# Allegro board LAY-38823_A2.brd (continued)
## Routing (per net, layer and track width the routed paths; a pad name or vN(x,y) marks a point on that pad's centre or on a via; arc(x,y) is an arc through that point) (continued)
ONOFF: length 23.2
  TOP w0.104: U1.A25 28.99,35.8 29.35,36.16 29.35,37.58 30.83,39.06 TP7.1 v1(31.38,40.19) 31.73,40.54 R21.2
  L3_IN1 w0.081: v1(31.38,40.19) 31.38,40.88 32.68,42.18 32.68,42.68 32.13,43.23 28.47,43.23 26.03,45.67 26.03,46.14 25.33,46.84 24.83,46.84 24.41,47.26 24.41,47.76 23.62,48.55 v1(22.78,48.55)
  BOTTOM w0.104: J4.46 22.47,49.18 22.78,48.86 v1(22.78,48.55)
PDM_CLK: length 21.2
  TOP w0.076: U1.AC15 24.44,24.71 v1(24.46,24.69)
  L3_IN1 w0.081: v1(24.46,24.69) 24.12,24.36 24.12,22.62 35.13,11.62 v1(35.28,11.62)
  BOTTOM w0.104: J5.65 34.85,11.19 v1(35.28,11.62)
PDM_DATA0: length 24.5
  TOP w0.076: U1.AD18 25.08,24.21 v1(25.03,24.15)
  L3_IN1 w0.081: v1(25.03,24.15) 25.13,24.05 25.13,22.24 34.99,12.37 35.43,12.37 37.22,10.58 v1(37.22,8.13)
  BOTTOM w0.104: v1(37.22,8.13) 35.61,8.13 35.25,8.48 J5.67
PDM_DATA1: length 20.7
  TOP w0.102: U1.AC14 v1(23.49,24.24)
  L3_IN1 w0.081: v1(35.27,10.32) 35.27,10.81 23.49,22.59 v1(23.49,24.24)
  BOTTOM w0.104: v1(35.27,10.32) 35.27,10.3 35.65,9.92 J5.69
PDM_DATA2: length 21.8
  TOP w0.076: v1(22.54,24.15) 22.59,24.21 U1.AD13
  L3_IN1 w0.081: v1(36.05,9.71) 35.06,9.71 34.69,10.08 34.69,10.8 22.64,22.85 22.64,24.06 v1(22.54,24.15)
  BOTTOM w0.104: J5.71 v1(36.05,9.71)
PDM_DATA3: length 23
  TOP w0.076: v1(22.54,24.71) 22.54,24.71 U1.AC13
  L3_IN1 w0.081: v1(22.54,24.71) 22.92,24.33 22.92,22.87 34.9,10.88 34.9,10.16 35.12,9.95 35.68,9.95 v1(36.05,10.32)
  BOTTOM w0.104: v1(36.05,10.32) 36.45,9.92 J5.73
PHY_VREF: length 1.9
  TOP w0.076: TP58.1 15.95,28.17 U1.P1
PMIC_NINT: length 37
  TOP w0.076: U1.AF13 23.25,22.96 23.25,22.53
  TOP w0.104: v1(24.51,17.14) 24.51,17.88 23.2,19.19 23.2,22.48 23.25,22.53
  TOP w0.203: U8.13 5.85,8.54 v2(5.74,8.43)
  BOTTOM w0.104: v2(5.74,8.43) 6.19,8.43 6.33,8.3 6.33,6.94 7.43,5.84 12.42,5.84 13.3,6.72 19.88,6.72 20.88,7.72 20.88,13.23 23.93,16.28 23.93,16.56 v1(24.51,17.14)
  BOTTOM w0.254: R61.1 5.19,8.43 v2(5.74,8.43)
PMIC_ON_REQ: length 87.7
  TOP w0.104: R51.1 18.48,15.42 18.67,15.42 19.2,15.95 19.2,18.04 17.46,19.79 14.73,19.79 13.59,20.93 2.44,20.93 1.31,22.06 v1(1.31,35.72) ; TP6.1 32.89,42.44 v1(32.1,42.44) 31.29,42.44 29.96,41.11 29.96,38.88 28.89,37.81 28.89,36.2 28.49,35.8 U1.A24
  L3_IN1 w0.081: v1(23.42,48.03) 23.42,47.66 24.88,46.2 24.88,45.73 27.79,42.82 31.72,42.82 v1(32.1,42.44)
  BOTTOM w0.104: J4.48 22.87,49.1 23.16,48.81 23.16,48.29 v1(23.42,48.03) 22.81,47.42 12.67,47.42 1.31,36.05 v1(1.31,35.72)
PMIC_STBY_REQ: length 69.9
  TOP w0.076: U1.E24 28.08,33.71 v1(28.06,33.7)
  TOP w0.104: v2(18.79,16.18) 18.69,16.08 R52.1 ; v1(23.27,7.76) 23.27,8.5 TP10.1 v2(19.33,8.72)
  L3_IN1 w0.076: 31.63,31.74 31.04,31.74 29.09,33.7 v1(28.06,33.7)
  L3_IN1 w0.081: 31.63,31.74 32.1,31.74 32.85,32.49 33.83,32.49 35.04,33.71 35.47,33.71 v1(35.86,33.31)
  BOTTOM w0.104: v1(35.86,33.31) 37.62,31.56 37.62,14.24 41.97,9.89 41.97,8.55 41.47,8.05 40.12,8.05 39.56,7.49 27.82,7.49 27.55,7.76 v1(23.27,7.76) ; v2(19.33,8.72) 19.52,8.91 19.52,15.5 18.85,16.18 v2(18.79,16.18)
POR_B: length 81.5
  TOP w0.076: U1.B24 28.75,35.46 28.75,35.81 29.12,36.18 29.12,37.49
  TOP w0.104: v1(24.04,47.57) 24.04,48.1 22.7,49.44 12.99,49.44 0.89,37.33 0.89,20.21 1.55,19.55 1.55,12.9 1.8,12.65 3.07,12.65 3.96,11.76 3.96,10.62 R114.2 ; 29.12,37.49 29.12,37.71 30.2,38.8 30.2,40.37 TP9.1 v1(31.39,41.55) 31.49,41.66 R20.2
  L3_IN1 w0.081: v1(24.04,47.57) 24.04,47.34 25.12,46.26 25.12,45.92 28.02,43.02 32.04,43.02 32.47,42.6 32.47,42.29 31.73,41.55 v1(31.39,41.55)
  BOTTOM w0.104: v1(24.04,47.57) 23.8,47.81 23.8,48.19 23.4,48.6 23.4,48.97 23.27,49.09 J4.50
QSPIA_DATA0: length 30.2
  TOP w0.076: U1.P23 v1(28.45,29.21)
  TOP w0.104: v1(40.99,42.48) 42.65,42.48 43.59,43.42 TP16.1
  L3_IN1 w0.081: v1(40.99,42.48) 41.24,42.23 41.24,39.78 40.52,39.06 40.52,34.85 38.32,32.65 38.32,32 35.53,29.21 v1(28.45,29.21)
  BOTTOM w0.104: U5.5 43.69,43.84 42.33,42.48 v1(40.99,42.48)
QSPIA_DATA1: length 27.6
  TOP w0.076: v1(28.59,30.74) 28.49,30.74 28.37,30.85 28.37,31.09 U1.K24
  L3_IN1 w0.081: v1(39.9,40.95) 39.9,40.39 39.45,39.94 39.45,36.54 37.24,34.33 37.24,32.53 34.99,30.28 29.95,30.28 29.32,30.91 28.77,30.91 28.6,30.74 v1(28.59,30.74)
  BOTTOM w0.104: v1(39.9,40.95) 39.95,40.9 39.95,40.8 41.16,39.6 45.63,39.6 46.23,39 U5.2
QSPIA_DATA2: length 26.8
  TOP w0.076: U1.K23 27.96,31.18 27.96,30.83 v1(28.03,30.76)
  L3_IN1 w0.081: v1(28.03,30.76) 28.03,30.98 28.17,31.12 29.69,31.12 30.18,30.63 35.05,30.63 37.03,32.61 37.03,34.59 39.22,36.78 39.22,40.35 v1(39.49,40.62)
  BOTTOM w0.104: v1(39.49,40.62) 39.49,40.6 41.65,38.44 42.63,38.44 43,38.08 44.55,38.08 44.96,38.49 U5.3
QSPIA_DATA3: length 28.7
  TOP w0.076: v1(28.05,30.16) 27.99,30.1 U1.N23
  L3_IN1 w0.081: v1(28.05,30.16) 28.38,29.83 35.13,29.83 37.78,32.48 37.78,34.08 40.05,36.35 40.05,39.59 40.82,40.36 40.82,41.22 40.68,41.36 v1(40.66,41.36)
  BOTTOM w0.104: U5.7 46.23,44.19 45.37,43.33 43.97,43.33 42,41.37 40.66,41.37 v1(40.66,41.36)
QSPIA_NSS0: length 29.7
  TOP w0.076: v1(28.6,30.17) 28.49,30.07 U1.N24
  L3_IN1 w0.081: v1(28.6,30.17) 28.72,30.05 35.06,30.05 37.57,32.57 37.57,34.2 39.66,36.3 39.66,39.74 40.45,40.53 v1(40.45,40.87)
  BOTTOM w0.104: R37.2 48.45,38.92 48.28,38.76 U5.1 47.5,39.02 46.66,39.85 41.47,39.85 v1(40.45,40.87)
QSPIA_SCLK: length 33.9
  TOP w0.076: U1.N22 v1(27.49,30.16)
  TOP w0.104: TP17.1 43.53,42.1 40.66,42.1 v1(40.64,42.08)
  L3_IN1 w0.081: v1(40.64,42.08) 40.69,42.08 41.03,41.73 41.03,40.1 40.27,39.34 40.27,34.93 38.03,32.68 38.03,32.26 35.32,29.55 28.1,29.55 v1(27.49,30.16)
  BOTTOM w0.104: U5.6 44.96,44.23 44.41,43.67 43.98,43.67 42.38,42.08 v1(40.64,42.08)
R_SNSP1: length 5.4
  TOP w0.203: U8.38 14.45,11.74 15.74,13.03 R193.2 R194.1
R_SNSP2: length 4.5
  TOP w0.203: R192.2 14.94,16.13 R191.1 12.5,15.11 12.21,14.82 U8.44
REF_CLK_32K: length 68.3
  TOP w0.104: U1.AG14 23.49,19.7 v1(24.93,18.27) ; v1(29.68,7.1) 30.09,7.51 R116.1
  L3_IN1 w0.081: v1(24.93,18.27) 30.78,12.41 30.78,8.21 v1(29.68,7.1)
  BOTTOM w0.104: R115.1 47.76,32.86 40.02,25.12 40.02,12.74 42.48,10.27 42.48,8.24 41.34,7.1 v1(29.68,7.1)
REG_PD_B: length 47.7
  TOP w0.076: U1.R23 v1(27.99,28.26)
  TOP w0.104: U9.12 63.72,36.29 59.95,40.06 50.75,40.06 48.53,37.84 48.53,32.33 47.38,31.18 42.9,31.18 40.09,28.37 38.96,28.37 38.53,27.94 36.12,27.94 v2(36,28.05)
  BOTTOM w0.076: 31.63,28.6 28.34,28.6 v1(27.99,28.26)
  BOTTOM w0.104: v2(36,28.05) 36,28.19 35.59,28.6 31.63,28.6
RF_ANT0: length 19.7
  TOP w0.279: J1.1 68.1,3.68 C457.1 C455.2
RTC_RESET_B: length 110.2
  TOP w0.076: v1(28.58,32.79) 28.57,32.79 28.49,32.86 U1.F24
  TOP w0.104: v2(4.57,11.05) 4.37,11.25 R111.2 ; v1(38.33,37.67) 38.33,39.14 39.08,39.89 39.08,42.49 38.95,42.62 TP8.1 39.25,43.68 R102.2 ; v2(20.09,5.79) 20.09,6.05 20.88,6.83 27.5,6.83 29.12,5.21 29.12,4.1 29.89,3.33 37.11,3.33 40.67,6.88 v1(40.67,7.67)
  L3_IN1 w0.081: v1(28.58,32.79) 28.65,32.79 28.66,32.8 29.71,32.8 30.98,31.54 32.19,31.54 32.93,32.29 35.87,32.29 36.23,32.65 36.23,35.57 v1(38.33,37.67)
  BOTTOM w0.104: v1(40.67,7.67) 41.46,7.67 42.2,8.41 42.2,10.06 37.94,14.33 37.94,34.94 38.33,35.34 v1(38.33,37.67) ; v2(4.57,11.05) 2.59,9.07 2.59,4.11 4.31,2.39 18.41,2.39 20.09,4.07 v2(20.09,5.79)
SAI2_MCLK: length 29
  TOP w0.076: v1(26.5,24.17) 26.43,24.17 26.39,24.21 U1.AD19
  L3_IN1 w0.081: v1(26.5,24.17) 26.42,24.09 26.42,21.58 35.18,12.83 35.56,12.83 37.86,10.53 37.86,5.61 36.35,4.09 35.75,4.09 35.25,4.6 v1(35.25,4.62)
  BOTTOM w0.104: J5.66 34.85,5.55 35.03,5.38 35.03,4.84 v1(35.25,4.62)
SAI2_RXC: length 21.7
  TOP w0.076: v1(27.45,25.69) 27.49,25.65 U1.AB22
  L3_IN1 w0.076: 28.7,25.02 30.06,23.65 30.06,21.21
  L3_IN1 w0.081: v1(32.3,18.75) 30.06,20.99 30.06,21.21 ; v1(27.45,25.69) 28.13,25.02 28.7,25.02
  BOTTOM w0.104: v1(32.3,18.75) 37.65,13.4 J5.79
SAI2_RXD: length 38.9
  TOP w0.076: v1(28.49,24.23) 28.49,24.24 U1.AC24
  L3_IN1 w0.081: v1(28.49,24.23) 28.04,23.79 28.04,21.14 31.1,18.08 39.03,18.08 40.3,19.35 v1(40.82,19.35)
  BOTTOM w0.104: v1(40.82,19.35) 41.16,19.7 41.16,24.82 48.13,31.78 R132.2
SAI2_RXD_RES: length 1.9
  TOP w0.104: v2(54.63,32.08) 54.6,32.12 U9.25
  BOTTOM w0.104: R132.1 54.53,31.78 54.63,31.89 v2(54.63,32.08)
SAI2_RXFS: length 28.9
  TOP w0.076: v1(26.49,24.73) 26.47,24.71 U1.AC19
  L3_IN1 w0.081: v1(35.41,5.19) 35.41,4.98 35.62,4.77 35.62,4.52 35.84,4.3 36.26,4.3 37.59,5.63 37.59,10.51 35.51,12.58 35.12,12.58 26.15,21.55 26.15,24.39 v1(26.49,24.73)
  BOTTOM w0.104: v1(35.41,5.19) 35.41,5.28 35.25,5.44 J5.68
SAI2_TXC: length 41.1
  TOP w0.076: v1(27.06,24.33) 27.18,24.21 U1.AD22
  L3_IN1 w0.081: v1(27.06,24.33) 27.14,24.25 27.14,21.16 30.84,17.46 39.86,17.46 v1(40.81,18.4)
  BOTTOM w0.104: v1(40.81,18.4) 41.39,18.99 41.39,24.65 48.17,31.43 52.05,31.43 52.27,31.21 R198.1 53.28,30.7 R131.2
SAI2_TXC_1P8: length 69.7
  TOP w0.104: v1(40.82,17.56) 41.17,17.21 41.17,6.6 37.64,3.07 26.52,3.07 25.68,3.91 25.68,5.49 24.61,6.55 21.89,6.55 21.51,6.17 21.51,3.66 20.91,3.06 19.96,3.06 19.32,3.69 18.42,3.69 17.61,4.5 R196.2 17.61,5.93 16.48,7.06 13.17,7.06 12.78,6.67 12.43,6.67 12.21,6.89 U8.27
  BOTTOM w0.104: v1(40.82,17.56) 41.62,18.37 41.62,24.51 47.82,30.7 R198.2
SAI2_TXC_3P3: length 30.2
  TOP w0.104: R203.1 v2(15.75,3.43)
  L3_IN1 w0.081: v2(15.75,3.43) 15.99,3.68 37.45,3.68 39.08,5.31 v2(39.08,9.85)
  BOTTOM w0.104: J5.87 39.25,9.68 v2(39.08,9.85)
SAI2_TXC_RES: length 2
  TOP w0.104: U9.26 54.47,31.22 v2(54.62,31.06)
  BOTTOM w0.104: R131.1 54.38,30.7 54.62,30.95 v2(54.62,31.06)
SAI2_TXD: length 40.7
  TOP w0.076: U1.AC22 27.26,24.71 v1(27.08,24.89)
  L3_IN1 w0.081: v1(27.08,24.89) 27.43,24.54 27.43,21.16 30.93,17.67 39.46,17.67 40.57,18.78 42.42,18.78 v1(42.48,18.84)
  BOTTOM w0.104: R130.2 R199.1 52.25,29.05 52.03,28.82 46.65,28.82 42.13,24.3 42.13,19.19 v1(42.48,18.84)
SAI2_TXD_1P8: length 66.2
  TOP w0.104: v1(42.5,18.31) 42.22,18.02 40.31,18.02 38.56,16.27 38.56,5.86 36.31,3.61 30.92,3.61 30.03,4.49 30.03,4.88 29.9,5.02 29.9,5.39 27.63,7.65 25.03,7.65 24.44,7.06 20.55,7.06 v2(19.26,5.78) ; v2(16.71,5.05) 16.65,5.1 16.65,5.28 R197.2 16.27,5.57 16.02,5.82 16.02,6.53 15.77,6.78 13.38,6.78 13.04,6.44 12.25,6.44 11.81,6.89 U8.26
  L3_IN1 w0.081: v2(19.26,5.78) 18.53,5.05 v2(16.71,5.05)
  BOTTOM w0.104: v1(42.5,18.31) 42.47,18.31 41.86,18.92 41.86,24.41 47.08,29.63 R199.2
SAI2_TXD_3P3: length 32.5
  TOP w0.104: R202.1 v2(14.68,3.4)
  L3_IN1 w0.081: v2(14.68,3.4) 15.16,3.88 36.48,3.88 38.68,6.09 38.68,10.06 v2(39.06,10.44)
  BOTTOM w0.104: J5.91 40.05,9.55 40.07,9.57 40.07,10 39.63,10.44 v2(39.06,10.44)
SAI2_TXD_RES: length 2
  TOP w0.104: v2(54.6,30.1) 54.38,30.32 U9.27
  BOTTOM w0.104: R130.1 54.25,29.63 54.6,29.98 v2(54.6,30.1)
SAI2_TXFS: length 38.2
  TOP w0.076: v1(28.01,24.65) 28.01,24.56 27.99,24.54 U1.AD23
  L3_IN1 w0.081: v1(42.51,19.39) 42.1,18.98 40.31,18.98 39.2,17.88 31.02,17.88 27.81,21.08 27.81,24.45 v1(28.01,24.65)
  BOTTOM w0.104: R129.2 46.86,28.56 42.42,24.12 42.42,19.49 v1(42.51,19.39)
SAI2_TXFS_RES: length 2.2
  TOP w0.104: v2(54.64,29.26) 54.48,29.42 U9.28
  BOTTOM w0.104: v2(54.64,29.26) 54.64,29.11 54.09,28.56 R129.1
SAI3_MCLK: length 19.9
  TOP w0.076: U1.AD6 19.87,24.21 19.9,24.17 v1(19.96,24.17)
  L3_IN1 w0.081: v1(29.65,10.32) 29.72,10.38 29.72,12.96 19.89,22.78 19.89,24.1 v1(19.96,24.17)
  BOTTOM w0.104: v1(29.65,10.32) 29.65,9.93 30.05,9.53 J5.41
SAI3_RXC: length 22
  TOP w0.104: v1(32.38,9.77) 32.34,9.82 32.34,9.83 30.1,12.06 24.75,12.06 19.99,16.82 U1.AG7
  BOTTOM w0.104: J5.53 32.45,9.7 v1(32.38,9.77)
SAI3_RXD: length 22.8
  TOP w0.076: U1.AF7 20.24,22.96 20.24,22.49
  TOP w0.104: 20.24,22.49 20.22,22.48 20.22,16.91 24.76,12.38 30.11,12.38 32.17,10.32 v1(32.42,10.32)
  BOTTOM w0.104: v1(32.42,10.32) 32.76,9.98 32.76,9.54 32.85,9.45 J5.55
SAI3_RXFS: length 22.4
  TOP w0.104: U1.AG8 20.46,22.67 20.46,17.01 24.74,12.73 30.67,12.73 v1(32.45,10.95)
  BOTTOM w0.104: J5.51 32.05,9.48 31.98,9.55 31.98,10.48 v1(32.45,10.95)
SAI3_TXC: length 21.1
  TOP w0.104: v1(30.38,10.34) 29.4,11.32 24.8,11.32 19.49,16.63 U1.AG6
  BOTTOM w0.104: J5.45 30.85,9.5 30.79,9.55 30.79,9.92 v1(30.38,10.34)
SAI3_TXD: length 22.2
  TOP w0.076: U1.AF6 19.74,22.96 19.74,22.52
  TOP w0.104: 19.74,22.52 19.74,16.71 24.76,11.68 29.71,11.68 v1(31.15,10.24)
  BOTTOM w0.104: J5.49 31.65,9.78 31.18,10.24 v1(31.15,10.24)
SAI3_TXFS: length 21.3
  TOP w0.076: U1.AC6 19.93,24.71 v1(19.96,24.74)
  L3_IN1 w0.081: v1(30.41,9.71) 29.66,9.71 29.28,10.09 29.28,13.1 19.61,22.76 19.61,24.39 v1(19.96,24.74)
  BOTTOM w0.104: v1(30.41,9.71) 30.45,9.67 J5.43
SAI5_MCLK: length 21.2
  TOP w0.076: U1.AD15 24.39,24.21 24.46,24.14 v1(24.47,24.14)
  L3_IN1 w0.081: v1(36.82,10.32) 36.82,10.6 35.26,12.17 34.87,12.17 24.4,22.63 24.4,24.08 v1(24.47,24.14)
  BOTTOM w0.104: J5.77 37.25,9.92 36.85,10.32 v1(36.82,10.32)
SAI5_RXFS: length 28.7
  TOP w0.076: U1.AB15 24.4,25.21 24.44,25.24
  TOP w0.084: 24.44,25.24 v1(24.45,25.25)
  L3_IN1 w0.081: v1(36.09,4.67) 36.29,4.67 36.55,4.92 36.55,6.66 36.42,6.78 36.42,10.47 36.2,10.69 35.68,10.69 23.84,22.53 23.84,24.64 v1(24.45,25.25)
  BOTTOM w0.104: v1(36.09,4.67) 35.99,4.67 35.79,4.87 35.79,5.35 35.65,5.49 J5.70
SD1_CLK: length 40.3
  TOP w0.076: U1.V26 29.75,26.96 30.4,26.96
  TOP w0.104: 30.4,26.96 33.48,26.96 33.96,26.47 41.38,26.47 44.1,29.19 44.7,29.19 44.8,29.08 44.8,28.98 44.9,28.87 45.11,28.87 45.22,28.98 45.22,29.08 45.32,29.19 45.53,29.19 45.63,29.08 45.63,28.98 45.74,28.87 45.95,28.87 46.05,28.98 46.05,29.08 46.15,29.19 46.36,29.19 46.47,29.08 46.47,28.98 46.57,28.87 46.78,28.87 46.88,28.98 46.88,29.08 46.99,29.19 47.66,29.19 50.73,32.25 50.73,37.87 51.76,38.9 57.74,38.9 TP66.1 58.96,37.68 R214.1
SD1_CLK_R: length 1.5
  TOP w0.104: R214.2 59.22,36.26 U9.17
SD1_CMD: length 39.6
  TOP w0.104: U1.V27 33.55,27.21 34.06,26.7 40.86,26.7 43.78,29.61 47.6,29.61 50.22,32.22 50.22,37.82 51.54,39.14 58.23,39.14 59.41,37.96 TP67.1 59.94,37.64 R213.1
SD1_CMD_R: length 1.5
  TOP w0.104: U9.16 60.12,36.34 R213.2
SD1_DATA0: length 37.7
  TOP w0.076: U1.Y27 31.63,26.21
  TOP w0.104: 31.63,26.21 33.24,26.21 33.68,25.77 42.64,25.77 44.43,27.56 47.82,27.56 51.88,31.62 51.88,37.62 52.47,38.21 55.8,38.21 56.29,37.72 57.43,37.72 57.64,37.93 TP24.1 57.98,37.8 R209.1
SD1_DATA0_R: length 1.6
  TOP w0.104: R209.2 58.32,36.17 U9.18
SD1_DATA1: length 36.8
  TOP w0.076: 30.4,25.96 29.74,25.96 U1.Y26
  TOP w0.104: R210.1 56.42,37.27 55.71,37.98 52.7,37.98 52.2,37.49 52.2,31.42 47.9,27.11 44.57,27.11 43,25.54 33.58,25.54 33.16,25.96 30.4,25.96
SD1_DATA1_R: length 1.6
  TOP w0.104: U9.19 57.42,36.09 R210.2
SD1_DATA2: length 41.5
  TOP w0.076: U1.T27 31.63,28.21
  TOP w0.104: R211.1 59.34,39.83 51,39.83 48.95,37.78 48.95,32.3 47.42,30.77 43.11,30.77 40.42,28.09 39.03,28.09 38.58,27.64 35.12,27.64 34.55,28.21 31.63,28.21
SD1_DATA2_R: length 1.4
  TOP w0.104: R211.2 61.91,35.12 U9.14
SD1_DATA3: length 41.2
  TOP w0.076: 30.25,27.96 29.75,27.96 U1.T26
  TOP w0.104: 30.25,27.96 34.48,27.96 35.02,27.41 38.73,27.41 39.18,27.86 40.73,27.86 43.27,30.4 47.46,30.4 49.37,32.3 49.37,37.75 51.21,39.6 58.97,39.6 60.92,37.64 R212.1
SD1_DATA3_R: length 1.4
  TOP w0.104: U9.15 61.02,36.42 R212.2
SD1_STROBE: length 42
  TOP w0.076: U1.R24 28.49,28.35 v1(28.58,28.26)
  L3_IN1 w0.081: v1(28.58,28.26) 28.62,28.3 34.92,28.3 38.54,31.92 38.54,32.58 41.45,35.48 41.45,43.21 39.14,45.52 34.7,45.52 33.29,46.93 31.54,46.93 30.92,47.55 28.17,47.55 27.85,47.87 v1(27.66,47.87)
  BOTTOM w0.104: v1(27.66,47.87) 27.62,47.87 27.25,48.25 27.25,48.94 27.27,48.96 J4.70
SD2_CLK: length 44.7
  TOP w0.076: v1(27.99,26.25) 27.99,26.25 U1.W23
  L3_IN1 w0.076: 42.07,39.54 42.07,34.78 40.56,33.27
  L3_IN1 w0.081: v1(27.99,26.25) 27.99,26.78 28.09,26.87 35.43,26.87 38.56,30 38.56,30.21 39.04,30.69 39.25,30.69 39.37,30.81 39.37,32.08 40.56,33.27 ; 42.07,39.54 42.07,43.63 39.32,46.38 34.72,46.38 33.25,47.86 31.7,47.86 31.18,48.37 28.57,48.37 28.49,48.45 v1(28.49,48.5)
  BOTTOM w0.104: v1(28.49,48.5) 28.49,48.64 28.47,48.66 J4.76
SD2_CMD: length 45.3
  TOP w0.076: v1(28.53,26.28) 28.49,26.31 U1.W24
  L3_IN1 w0.076: 42.3,39.78 42.3,34.63 40.56,32.89
  L3_IN1 w0.081: v1(28.91,48.83) 29.2,49.11 30.97,49.11 31.89,48.2 33.25,48.2 34.53,46.92 39.13,46.92 42.3,43.75 42.3,39.78 ; v1(28.53,26.28) 28.56,26.28 28.63,26.34 35.2,26.34 39.62,30.77 39.62,31.95 40.56,32.89
  BOTTOM w0.076: v1(28.53,26.28) 28.61,26.36 29.26,26.36 29.7,25.92 R120.2
  BOTTOM w0.104: J4.78 28.87,48.93 28.91,48.88 v1(28.91,48.83)
SD2_DATA0: length 50
  TOP w0.076: v1(28.03,25.7) 27.99,25.66 U1.AB23
  L3_IN1 w0.081: v1(35.66,47.59) 35.82,47.43 39.75,47.43 43.83,43.35 43.83,36.82 43.47,36.46 43.47,33.8 41.33,31.66 41.33,31.13 35.63,25.43 28.28,25.43 28.03,25.68 v1(28.03,25.7)
  BOTTOM w0.076: 29.54,25.43 28.48,25.43 28.37,25.54 28.26,25.54 28.1,25.7 v1(28.03,25.7)
  BOTTOM w0.104: J4.84 30.07,49.02 31.59,47.49 33.55,47.49 33.82,47.76 35.49,47.76 v1(35.66,47.59) ; 29.54,25.43 30.93,25.43 R119.2
SD2_DATA1: length 44.5
  TOP w0.076: U1.AB24 28.49,25.65 v1(28.62,25.77)
  L3_IN1 w0.081: v1(35.16,47.38) 35.16,47.3 35.24,47.22 39.22,47.22 42.51,43.93 42.51,33.56 40.96,32.01 40.96,31.05 35.55,25.65 28.74,25.65 v1(28.62,25.77)
  BOTTOM w0.104: v1(35.16,47.38) 34.77,47 34.39,47 34.12,47.26 31.5,47.26 29.67,49.09 J4.82
SD2_DATA2: length 43.6
  TOP w0.076: U1.V24 28.49,27.61 v1(28.57,27.68)
  L3_IN1 w0.081: v1(27.63,48.41) 27.65,48.41 28.3,47.76 31.01,47.76 31.63,47.14 33.38,47.14 34.79,45.73 39.27,45.73 41.65,43.34 41.65,35.4 38.75,32.49 38.75,31.77 34.93,27.94 31.71,27.94 31.56,27.78 31.56,27.59 31.48,27.51 31.31,27.51 31.23,27.59 31.23,27.78 31.15,27.87 30.99,27.87 30.91,27.78 30.91,27.59 30.83,27.51 30.66,27.51 30.58,27.59 30.58,27.78 30.5,27.87 30.34,27.87 30.26,27.78 30.26,27.59 30.18,27.51 28.74,27.51 v1(28.57,27.68)
  BOTTOM w0.104: J4.72 27.67,48.44 v1(27.63,48.41)
SD2_DATA3: length 44.6
  TOP w0.076: v1(28.02,27.69) 27.99,27.67 U1.V23
  L3_IN1 w0.081: v1(28.02,27.69) 28.42,27.28 32.27,27.28 32.36,27.36 32.36,27.48 32.44,27.56 32.6,27.56 32.68,27.48 32.68,27.36 32.76,27.28 32.92,27.28 33.01,27.36 33.01,27.48 33.09,27.56 33.25,27.56 33.33,27.48 33.33,27.36 33.41,27.28 33.57,27.28 33.66,27.36 33.66,27.48 33.74,27.56 33.9,27.56 33.98,27.48 33.98,27.36 34.06,27.28 34.67,27.28 39.09,31.7 39.09,32.18 41.86,34.95 41.86,43.45 39.38,45.94 34.87,45.94 33.26,47.55 31.51,47.55 31.06,48.01 28.34,48.01 28.07,48.28 v1(28.07,48.83)
  BOTTOM w0.104: J4.74 v1(28.07,48.83)
SD2_NCD: length 50.7
  TOP w0.076: 30.31,25.46 29.74,25.46 U1.AA26
  TOP w0.104: v1(33.84,24.93) 33.54,24.93 33.01,25.46 30.31,25.46
  L3_IN1 w0.076: 44.85,31.36 45.45,31.96
  L3_IN1 w0.081: 44.85,31.36 43.9,30.4 41.57,30.4 35.73,24.56 34.21,24.56 v1(33.84,24.93) ; 45.45,31.96 47.12,33.62 47.12,41.96 46.89,42.19 46.88,42.19 40.2,48.87 36.9,48.87 v1(36.37,48.34)
  BOTTOM w0.104: v1(36.37,48.34) 36.29,48.26 33.64,48.26 33.34,47.95 31.78,47.95 30.87,48.87 J4.88
SD2_NRST: length 52.1
  TOP w0.076: U1.AB26 29.74,24.96 30.35,24.96
  TOP w0.104: 30.35,24.96 32.31,24.96 v1(32.45,24.83)
  L3_IN1 w0.076: 45.45,31.43 45.38,31.36
  L3_IN1 w0.081: 45.45,31.43 47.37,33.35 47.37,42 47.02,42.35 46.97,42.4 46.97,42.4 40.14,49.23 35.81,49.23 v1(35.29,48.71) ; 45.38,31.36 44.12,30.1 41.56,30.1 35.82,24.36 32.92,24.36 v1(32.45,24.83)
  BOTTOM w0.104: J4.90 31.27,48.8 31.88,48.19 33.24,48.19 33.55,48.49 35.07,48.49 v1(35.29,48.71) ; R133.2 v1(32.45,24.83)
SD2_VSEL: length 23.5
  TOP w0.104: U8.29 14.69,8.14 15.16,7.67 17.17,7.67 17.63,8.13 v2(20.42,8.13)
  TOP w0.112: U1.AG12 22.49,18.36 v1(23.36,17.49)
  BOTTOM w0.104: v2(20.42,8.13) 20.47,8.18 20.47,13.18 23.36,16.07 v1(23.36,17.49)
SD2_WP: length 48.2
  TOP w0.104: U1.AA27 33.09,25.71 33.48,25.31 34,25.31 v1(34.38,24.93)
  L3_IN1 w0.081: v1(34.38,24.93) 35.81,24.93 41.48,30.61 43.66,30.61 45.93,32.88 45.93,42.69 40.98,47.63 40.11,47.63 40.11,47.63 36.36,47.63 36.2,47.79 v1(36.2,47.83)
  BOTTOM w0.104: v1(36.2,47.83) 36.17,47.83 35.97,48.03 33.76,48.03 33.45,47.72 31.69,47.72 30.47,48.94 J4.86
SD3_CLK: length 21.2
  TOP w0.076: U1.R26 29.74,28.46 31.63,28.46 ; 41.44,31.36 42.29,32.21 42.29,32.97 42.42,33.1 43.79,33.1 U4.M6
  TOP w0.104: 31.63,28.46 37.93,28.46 TP34.1 38.45,28.37 39.01,28.93 39.16,28.93 39.45,28.64 39.6,28.64 39.74,28.78 39.74,28.93 39.45,29.22 39.45,29.37 39.6,29.52 39.75,29.52 40.04,29.23 40.19,29.23 40.33,29.37 40.33,29.52 40.04,29.81 40.04,29.96 40.19,30.11 40.34,30.11 40.63,29.81 40.78,29.81 40.92,29.96 40.92,30.11 40.63,30.4 40.63,30.55 40.78,30.7 40.93,30.7 41.22,30.4 41.37,30.4 41.51,30.55 41.51,30.7 41.22,30.99 41.22,31.14 41.44,31.36
SD3_CMD: length 20.1
  TOP w0.076: 41.29,33.59 41.71,33.59 41.78,33.67 41.78,33.74 41.78,33.91 41.79,33.92 41.79,33.95 41.93,34.09 42.7,34.09 42.8,34.2 43.22,34.2 43.54,33.88 U4.M5 ; 31.63,28.71 U1.R27
  TOP w0.104: 31.63,28.71 37.12,28.71 37.68,29.27 TP35.1 37.68,29.55 38.16,30.03 R118.2 38.41,30.27 38.74,30.61 40.22,30.61 40.77,31.16 40.77,31.61 40.83,31.66 41.32,31.66 41.42,31.77 41.42,32.09 41.26,32.25 40.24,32.25 40.14,32.36 40.14,32.54 41.18,33.59 41.29,33.59
SD3_DATA0: length 20.9
  TOP w0.076: U1.M26 29.49,30.12 29.66,29.96 31.63,29.96
  TOP w0.104: 31.63,29.96 36.34,29.96 37.52,31.14 37.52,31.63 38.21,32.32 TP36.1 38.21,33.17 R117.2 38.75,33.32 39.25,33.81 39.25,34.74 39.42,34.91 39.83,34.91 40,35.08 40,38.76 40.55,39.31 42.23,39.31 42.54,39.01 U4.A3
SD3_DATA1: length 21.1
  TOP w0.076: 43.04,39.21 U4.A4 ; U1.L26 29.74,30.46 31.63,30.46
  TOP w0.104: 43.04,39.21 42.46,39.78 40.36,39.78 39.54,38.96 39.54,35.94 37.4,33.8 37.4,32.17 37.06,31.82 37.06,31.33 36.19,30.46 31.63,30.46
SD3_DATA2: length 22.1
  TOP w0.076: U1.K26 29.75,30.96 31.63,30.96
  TOP w0.104: U4.A5 43.54,39.62 42.9,40.26 40.18,40.26 39.07,39.15 39.07,36.13 36.94,33.99 36.94,32.36 36.6,32.02 36.6,31.53 36.03,30.96 31.63,30.96
SD3_DATA3: length 21.7
  TOP w0.076: 41.35,38.6 41.78,38.6 U4.B2 ; 31.63,29.46 29.75,29.46 U1.N26
  TOP w0.104: 41.35,38.6 40.78,38.6 40.53,38.35 40.53,37.54 40.64,37.43 40.91,37.43 41.01,37.33 41.01,37.12 40.91,37.02 40.64,37.02 40.53,36.91 40.53,36.7 40.64,36.6 40.91,36.6 41.01,36.49 41.01,36.29 40.91,36.18 40.64,36.18 40.53,36.08 40.53,35.87 40.64,35.77 40.91,35.77 41.01,35.66 41.01,35.51 40.91,35.41 40.7,35.41 40.53,35.24 40.53,33.92 40.16,33.55 39.75,33.55 38.9,32.7 38.9,32.29 37.98,31.37 37.98,30.95 36.49,29.46 31.63,29.46
SD3_DATA4: length 21.5
  TOP w0.076: 41.44,39.12 42.14,39.12 42.29,38.96 42.29,38.59 U4.B3 ; 31.63,29.71 U1.N27
  TOP w0.104: 41.44,39.12 40.86,39.12 40.25,38.5 40.25,34.02 40.15,33.92 39.99,33.92 39.89,34.03 39.89,34.52 39.79,34.62 39.6,34.62 39.5,34.52 39.5,33.65 38.65,32.79 38.65,32.36 37.75,31.47 37.75,31.05 36.42,29.71 31.63,29.71
SD3_DATA5: length 20.7
  TOP w0.076: U1.M27 31.63,30.21 ; 42.74,39.14 42.79,39.1 42.79,38.59 U4.B4
  TOP w0.104: 42.74,39.14 42.34,39.55 40.45,39.55 39.77,38.86 39.77,35.84 37.63,33.71 37.63,32.07 37.29,31.73 37.29,31.24 36.26,30.21 31.63,30.21
SD3_DATA6: length 21.6
  TOP w0.076: 43.29,39.07 43.29,38.59 U4.B5 ; U1.L27 31.63,30.71
  TOP w0.104: 31.63,30.71 36.11,30.71 36.83,31.43 36.83,31.92 37.17,32.26 37.17,33.9 39.3,36.03 39.3,39.05 40.26,40.01 42.69,40.01 43.29,39.41 43.29,39.07
SD3_DATA7: length 22.5
  TOP w0.076: U1.K27 31.63,31.21 ; 43.79,39.13 43.79,38.59 U4.B6
  TOP w0.104: 31.63,31.21 35.95,31.21 36.37,31.62 36.37,32.11 36.71,32.45 36.71,34.09 38.84,36.22 38.84,39.33 40,40.49 43,40.49 43.79,39.7 43.79,39.13
SD3_STROBE: length 21.4
  TOP w0.076: 31.63,29.21 U1.P27 ; 41.41,35.09 42.68,35.09 43.14,35.54 43.34,35.54 U4.H5
  TOP w0.104: 41.41,35.09 41.28,35.22 40.91,35.22 40.75,35.06 40.75,34.84 40.85,34.73 41.14,34.73 41.22,34.65 41.22,34.29 41.12,34.19 40.88,34.19 40.77,34.08 40.77,33.44 40.64,33.31 39.85,33.31 39.18,32.64 39.18,32.3 39.28,32.19 39.88,32.19 39.97,32.1 39.97,31.91 39.82,31.76 39.82,31.35 39.64,31.17 39.25,31.17 39.15,31.27 39.15,31.82 39.04,31.92 38.86,31.92 38.43,31.49 TP40.1 38.43,31.01 36.63,29.21 31.63,29.21
SPDIF_EXT_CLK: length 23.8
  TOP w0.076: 20.74,22.5 20.74,22.96 U1.AF8
  TOP w0.104: v1(33.91,10.47) 33.9,10.47 31.27,13.09 24.84,13.09 20.74,17.2 20.74,22.5
  BOTTOM w0.104: J5.63 34.45,9.93 v1(33.91,10.47)
SPDIF_RX: length 26
  TOP w0.104: U1.AG9 21.03,22.67 21.03,17.32 24.88,13.47 31.58,13.47 34.29,10.77 34.29,9.69 34.06,9.47 33.75,9.47 33.52,9.69 33.52,10.21 v1(33.25,10.49)
  BOTTOM w0.104: J5.59 33.65,9.57 33.52,9.69 33.52,10.21 v1(33.25,10.49)
SPDIF_TX: length 25.8
  TOP w0.076: U1.AF9 21.24,22.96 21.24,22.54
  TOP w0.104: 21.24,22.54 21.26,22.51 21.26,17.46 24.84,13.88 31.65,13.88 34.52,11.01 34.52,9.6 34.16,9.24 33.65,9.24 33.14,9.75 v1(33.14,9.79)
  BOTTOM w0.104: v1(33.14,9.79) 33.14,9.75 33.25,9.64 J5.57
SW_EN: length 1.6
  TOP w0.104: R137.2 5.41,8.94 U8.12
SWOUT_3V3: length 5.3
  TOP w0.152: TP68.1 13.01,5.15 12.5,5.67 11.76,5.67 11.4,6.03 11.15,6.03 v2(10.83,6.35)
  TOP w0.203: U8.23 10.61,6.58 v2(10.83,6.35)
  BOTTOM w0.381: v2(10.83,6.35) 10.75,6.43 C273.2
SYS_NRST: length 14.9
  TOP w0.152: R127.1 21.33,2.95 v1(21.67,2.95)
  BOTTOM w0.104: J5.39 29.65,7.97 29.4,7.72 28.07,7.72 27.64,8.16 22.89,8.16 21.67,6.94 v1(21.67,2.95)
SYS_STATUS: length 27
  TOP w0.076: 31.63,28.96 29.74,28.96 U1.P26
  TOP w0.104: 31.63,28.96 36.72,28.96 38.69,30.93 39.95,30.93 40.23,31.21 v2(40.23,31.57)
  BOTTOM w0.104: v2(40.23,31.57) 39.34,32.46 39.34,40 38.14,41.2 38.14,44.27 Q1.1
TS_RES_EXT: length 2.2
  TOP w0.076: U1.J24 28.49,32.06 v1(28.59,32.16)
  BOTTOM w0.076: R103.1 29.73,31.61 29.34,32 28.75,32 v1(28.59,32.16)
TS_TEST_OUT: length 8.9
  TOP w0.076: U1.J23 27.99,32.13 v1(28.04,32.17)
  TOP w0.104: TP19.1 35.49,31.69 33.53,31.69 v1(33.37,31.85)
  L3_IN1 w0.081: v1(28.04,32.17) 28.4,31.81 30.22,31.81 30.7,31.33 32.75,31.33 33.27,31.85 v1(33.37,31.85)
UART1_CTS: length 3.6
  TOP w0.076: v1(25.03,33.71) 25.03,33.71 U1.E18
  BOTTOM w0.104: v1(25.03,33.71) 25.43,34.11 25.43,36.44 R205.2
UART1_RTS: length 3.3
  TOP w0.076: v1(25.04,34.26) 25.09,34.21 U1.D18
  BOTTOM w0.104: R208.2 25.18,35.62 25.18,34.41 v1(25.04,34.26)
UART1_RXD: length 3
  TOP w0.076: U1.E14 v1(23.49,34.18)
  BOTTOM w0.104: v1(23.49,34.18) 23.49,36.25 R207.2
UART1_TXD: length 4.5
  TOP w0.076: v1(22.53,33.14) 22.59,33.21 U1.F13
  BOTTOM w0.104: R206.2 23.06,35.6 23.06,33.75 22.53,33.22 v1(22.53,33.14)
UART2_RXD: length 18.4
  TOP w0.076: v1(24.46,33.26) 24.41,33.21 U1.F15
  L3_IN1 w0.081: v1(24.46,33.26) 24.39,33.26 23.87,33.78 23.87,41.16 21.33,43.7 21.33,47.91 20.77,48.47 v1(20.77,48.69)
  BOTTOM w0.104: v1(20.77,48.69) 20.7,48.76 20.7,48.82 20.47,49.05 J4.36
UART2_TXD: length 17.7
  TOP w0.076: v1(24.48,33.77) 24.42,33.71 U1.E15
  L3_IN1 w0.081: v1(21.29,48.47) 21.64,48.13 21.64,43.97 24.14,41.47 24.14,34.06 24.43,33.77 v1(24.48,33.77)
  BOTTOM w0.104: J4.38 20.87,49.13 21.21,48.79 21.21,48.6 21.29,48.51 v1(21.29,48.47)
UART3_CTS: length 17.7
  TOP w0.114: v1(19.86,36.24) 19.99,36.11 U1.A7
  L3_IN1 w0.081: v1(19.86,36.24) 19.86,36.83 19.33,37.36 19.33,38.39 16.24,41.48 15.88,41.48 13.19,44.18 13.19,46.59 v1(14.88,48.28)
  BOTTOM w0.104: v1(14.88,48.28) 14.96,48.28 15.06,48.39 15.06,48.47 15.27,48.67 J4.10
UART3_RTS: length 20
  TOP w0.076: U1.B6 19.74,35.46 19.74,35.81 19.45,36.1
  TOP w0.084: 18.99,37.25 19.45,36.79 19.45,36.1
  TOP w0.104: 18.99,37.25 18.99,38.31 17.66,39.64 14.68,39.64 12.15,42.17 12.15,47.58 13.39,48.83 v1(13.64,48.83)
  BOTTOM w0.104: J4.2 13.67,48.86 v1(13.64,48.83)
UART3_RXD: length 19.2
  TOP w0.076: v1(19.96,34.27) 19.9,34.21 U1.D6
  L3_IN1 w0.081: v1(13.61,48.29) 12.98,47.66 12.98,44.05 15.75,41.28 15.94,41.28 19.08,38.14 19.08,37.14 19.33,36.88 19.33,34.89 v1(19.96,34.27)
  BOTTOM w0.104: v1(13.61,48.29) 13.65,48.29 14.07,48.72 J4.4
UART3_TXD: length 20.2
  TOP w0.076: 19.23,37.49 19.23,37.28 19.84,36.68 19.94,36.68 20.24,36.38 20.24,35.46 U1.B7
  TOP w0.104: 19.23,37.49 19.23,38.41 17.72,39.92 14.82,39.92 12.47,42.27 12.47,46.02 14.34,47.89 v1(14.34,48.27)
  BOTTOM w0.104: v1(14.34,48.27) 14.34,48.91 14.47,49.04 J4.6
UART4_RXD: length 19.9
  TOP w0.076: U1.F19 26.45,33.21 v1(26.49,33.17)
  L3_IN1 w0.081: v1(22.85,48.02) 22.85,47.92 24.06,46.72 24.06,42.8 25.59,41.27 25.59,34.07 v1(26.49,33.17)
  BOTTOM w0.104: J4.40 21.27,49.08 21.67,48.67 21.67,47.99 21.87,47.8 22.63,47.8 v1(22.85,48.02)
UART4_TXD: length 18.6
  TOP w0.076: U1.F18 25.09,33.21 v1(25.04,33.16)
  L3_IN1 w0.081: v1(25.04,33.16) 25.38,33.51 25.38,41.04 23.83,42.59 23.83,46.52 22.17,48.18 v1(22.17,48.26)
  BOTTOM w0.104: v1(22.17,48.26) 22.01,48.26 21.91,48.36 21.91,48.77 21.67,49.01 J4.42
USB1_DN: length 14
  TOP w0.091: v1(30.63,45.02) 30.65,45.02 30.87,45.24 31.13,45.24 31.24,45.13 31.24,44.54 28.77,42.06 28.77,39.29 27.55,38.07 27.55,35.77 U1.A22
  BOTTOM w0.091: J4.83 30.07,45.83 30.21,45.69 30.21,45.02 30.3,44.93 30.55,44.93 v1(30.63,45.02)
USB1_DP: length 14
  TOP w0.076: U1.B22 27.49,35.29 27.74,35.54 27.74,36.33 27.77,36.36
  TOP w0.091: 27.77,36.36 27.77,37.98 28.99,39.2 28.99,41.97 31.46,44.45 31.46,45.22 31.22,45.46 30.75,45.46 v1(30.66,45.55)
  BOTTOM w0.091: J4.85 30.47,46.42 30.31,46.26 30.31,45.89 v1(30.66,45.55)
USB1_ID: length 14.7
  TOP w0.076: v1(27.06,34.25) 27.1,34.21 U1.D22
  L3_IN1 w0.076: v1(27.06,34.25) 27.07,34.25 27.07,37.49
  L3_IN1 w0.081: 27.07,37.49 27.07,39.39 v1(30.12,42.45)
  BOTTOM w0.104: J4.89 31.27,43.59 30.19,42.51
  BOTTOM w0.114: 30.19,42.51 v1(30.12,42.45)
USB1_VBUS: length 12.5
  BOTTOM w0.203: 29.67,44.5 J4.81
  BOTTOM w0.254: R108.2 27.68,36.57 C393.1 27.68,36.59 29.67,38.57 29.67,44.5 29.67,44.5
VSYS_5V: length 17.2
  TOP w0.203: U8.56 6.97,14.19 v2(6.2,14.97) ; U8.53 8.61,14.91 8.34,15.18 v2(8.34,15.32)
  TOP w0.254: R195.2 16.63,8.67 16.53,8.76 15.53,8.76 14.49,9.8 v2(14.25,9.8)
  TOP w0.381: TP51.1 22.86,5.83 22.86,5.16 22.89,5.13 22.86,5.11 v2(22.91,5.06)
  BOTTOM w0.254: v2(6.2,14.97) 6.16,14.93 C13.1 ; v2(7.9,6.48) 7.9,6.89 C302.1 ; v2(8.34,15.32) 8.34,15.12 9.29,14.17 C272.1 ; C453.1 10.36,14.73 v2(10.36,15.04)
  BOTTOM w0.381: C295.1 8.66,6.7 v2(8.46,6.5) ; v2(10.92,15.01) 11.35,15.01 12.22,14.14 C301.1 ; C279.1 13.84,10.74 v2(14.22,10.36) ; C281.1 13.51,9.07 v2(14.25,9.8)
  vias: v2(22.23,10.49) v2(22.23,9.88) v2(22.33,5.06) v2(22.33,4.45) v2(22.81,10.49) v2(22.81,9.88) v2(22.91,4.45)
WDOG_B: length 21.4
  TOP w0.104: U1.AG13 22.97,22.69 22.97,18.76 24.08,17.65 24.08,16.86 v1(24.56,16.38) ; v1(20.96,5.77) 20.82,5.63 R55.1 20.82,4.14 TP53.1
  BOTTOM w0.104: v1(20.96,5.77) 21.26,6.07 21.26,13 24.56,16.31 v1(24.56,16.38)
WIFI_1V8: length 13.6
  TOP w0.279: U7.A2 57.72,43.18 TP13.1
  TOP w0.508: v2(54.72,36.11) U9.22 ; TP13.1 57.94,43.17 58.82,42.3 59.03,42.3 v2(59.03,40.49)
  BOTTOM w0.305: C454.1 54.74,36.08 v2(54.72,36.11)
  BOTTOM w0.508: v2(54.72,36.11) 54.72,38.02 57.19,40.49 v2(59.03,40.49)
WL_WAKE_DEV: length 32.1
  TOP w0.076: U1.U27 31.63,27.71
  TOP w0.104: U9.39 v2(59.22,24.73) ; 31.63,27.71 34.19,27.71 34.74,27.16 39.24,27.16 v2(39.46,27.38)
  L3_IN1 w0.081: v2(39.46,27.38) 39.69,27.61 50.35,27.61 53.59,24.37 58.85,24.37 v2(59.22,24.73)
WL_WAKE_HOST: length 44.9
  TOP w0.076: U1.W26 29.75,26.46 30.33,26.46
  TOP w0.104: v2(62.82,36.21) U9.13 ; v2(56.39,38.2) 56.36,38.2 56.13,38.44 52.27,38.44 51.49,37.66 51.49,31.79 47.62,27.92 44.07,27.92 42.16,26.01 33.77,26.01 33.32,26.46 30.33,26.46
  BOTTOM w0.104: v2(56.39,38.2) 57.23,39.05 59.98,39.05 v2(62.82,36.21)
XIN_32K: length 5.6
  TOP w0.104: U8.10 3.75,9.74 C298.1 1.99,9.92 1.87,10.04 QZ2.2
XOUT_32K: length 5.5
  TOP w0.104: U8.11 3.82,9.34 C299.1 1.99,9.11 1.87,8.98 QZ2.1
XTALI_24M: length 9.6
  TOP w0.076: U1.B27 30.08,35.21 31.32,36.45 31.63,36.45
  TOP w0.104: R26.1 33.7,37.64 C123.1 35.11,38.53 Y1.3 35.72,39.11 35.72,39.67 TP38.1 ; 31.86,36.45 31.63,36.45
  TOP w0.114: R26.1 33.25,37.63 32.84,37.22 32.84,36.87 32.42,36.45 31.86,36.45
XTALI_32K: length 10.7
  TOP w0.076: 29.91,37.49 29.79,37.37 29.79,36.01 U1.A26
  TOP w0.104: R100.2 36.66,41.31 35.68,40.33 34,40.33 TP39.1 33.57,39.91 32.33,39.91 29.91,37.49
XTALO_24M: length 10.6
  TOP w0.076: 31.63,36.15 31.28,36.15 30.09,34.96 29.74,34.96 U1.C26
  TOP w0.104: 31.63,36.15 31.79,36.15 ; R26.2 C124.1 34.05,36.01 34.19,36.14 34.19,37.16 34.34,37.31 35.84,37.31 36.73,36.43 Y1.1
  TOP w0.114: R26.2 33.18,36.88 32.45,36.15 31.79,36.15
XTALO_32K: length 11.5
  TOP w0.076: U1.B25 29.25,35.46 29.25,35.81 29.58,36.15 29.58,37.49
  TOP w0.104: R113.2 35.87,42.08 35.87,40.92 35.57,40.62 33.37,40.62 32.89,40.14 32.23,40.14 29.58,37.49
N102271152: length 2
  TOP w0.076: U1.P2 17.25,29.46 16.83,29.46
  TOP w0.114: v1(16.37,29.07) 16.45,29.16 16.53,29.16 16.83,29.46
  BOTTOM w0.107: R7.2 16.4,29.06 16.38,29.07 v1(16.37,29.07)
N106370682: length 2.3
  TOP w0.254: U1.F22 v1(27.49,32.78)
  BOTTOM w0.254: R108.1 27.68,34.45 27.51,34.28 27.51,32.79 v1(27.49,32.78)
N106370752: length 9.5
  TOP w0.076: U1.E19 26.47,33.71 v1(26.48,33.72)
  L3_IN1 w0.081: v1(27.33,41.76) 26.29,40.72 26.29,33.9 26.47,33.72 v1(26.48,33.72)
  BOTTOM w0.104: R29.1 27.39,41.83 v1(27.33,41.76)
N106740715: length 1.6
  TOP w0.104: U8.9 6.1,10.14 5.93,9.97 5.36,9.97 R114.1
N106743010: length 8.6
  TOP w0.104: U8.28 16.66,7.29 R106.2 19.33,5.03 R55.2
N106743238: length 5.1
  TOP w0.107: R51.2 17.34,15.04 14.45,12.14 U8.39
N106743319: length 5.8
  TOP w0.107: U8.40 14.52,12.54 16.91,14.94 16.91,15.61 R52.2
N106743947: length 1.6
  TOP w0.203: U8.6 5.97,11.34 5.91,11.28 5.53,11.28 R111.1
N107005929: length 3.5
  TOP w0.076: 15.22,29.04 15.68,29.5 16.43,29.5 16.89,29.96 17.25,29.96 U1.N2
  TOP w0.104: 15.22,29.04 14.91,28.73 TP15.1
N108008688: length 27.1
  TOP w0.104: U8.8 5.84,10.54 v2(5.72,10.42)
  TOP w0.203: R127.2 19.88,2.44 19.29,3.04 v1(18.39,3.04)
  BOTTOM w0.104: v2(5.72,10.42) 4.45,10.42 2.9,8.87 2.9,4.24 4.39,2.76 18.11,2.76 v1(18.39,3.04)
N108250870: length 1
  TOP w0.254: v1(24.49,34.27) 24.42,34.21 U1.D15
  BOTTOM w0.254: C268.1 24.02,34.27 v1(24.49,34.27)
N109411711: length 2.6
  TOP w0.254: U8.30 14.97,8.54 15.33,8.18 R195.1
N109413799: length 6.5
  TOP w0.107: U8.41 14.59,12.94 16.64,14.99 16.64,16.07 17.38,16.82 R48.2
N109414410: length 7
  TOP w0.107: R54.2 16.97,17.61 16.97,16.74 16.4,16.17 16.4,15.09 14.66,13.34 U8.42
N109458619: length 1.4
  TOP w0.254: U4.K5 v1(43.99,33.89)
  BOTTOM w0.254: TP18.1 44.06,33.82 v1(43.99,33.89)
N109477029: length 1.8
  TOP w0.104: D1.C 40.72,43.31 v1(40.59,43.18)
  BOTTOM w0.104: v1(40.59,43.18) 40.47,43.3 Q1.3
N109477483: length 2.6
  TOP w0.076: v1(27.42,28.26) 27.49,28.32 U1.R22
  BOTTOM w0.076: C245.1 28.66,28.83 28,28.83 v1(27.42,28.26)
N109540553: length 7.4
  TOP w0.104: R203.2 15.34,5.25 R201.2 15.71,5.6 15.77,5.66 15.77,6.37 15.6,6.55 13.66,6.55 13.32,6.21 12.09,6.21 11.41,6.89 U8.25
N109540574: length 5.1
  TOP w0.104: R202.2 14.68,5.09 R200.2 14.1,5.6 13.72,5.98 11.92,5.98 11.01,6.89 U8.24
N109586960: length 9.3
  TOP w0.084: v1(10.16,31.85) 10.07,31.85 U2.G11
  TOP w0.104: v1(8.56,29.46) 9.19,28.83 11.48,28.83 12.67,27.63 R204.1
  BOTTOM w0.084: v1(10.16,31.85) 9.82,31.51 9.1,31.51 8.56,30.96 v1(8.56,29.46)
N109688415: length 5.1
  TOP w0.254: TP12.1 57.48,41.6 C148.1 55.99,41.6 R153.2 55.28,41.59 R215.1
  TOP w0.279: U7.B1 55.99,41.6 C148.1
N1094770141: length 1.4
  TOP w0.305: R125.2 41.77,45.22 D1.A

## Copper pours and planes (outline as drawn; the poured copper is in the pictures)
GND on BOTTOM (solid shape): 25.75,13.08 25.75,8.65 25.55,8.65 25.55,9.49 25.35,9.49 25.35,8.65 25.15,8.65 25.15,9.49 24.95,9.49 24.95,8.65 24.75,8.65 24.75,9.49 24.55,9.49 24.55,8.65 24.35,8.65 24.35,9.49 24.15,9.49 24.15,8.65 23.95,8.65 23.95,9.49 23.75,9.49 23.75,8.65 23.55,8.65 23.55,10.53 23.28,10.8 23.28,13.32 23.47,13.5 25.33,13.5
GND on BOTTOM (solid shape): 23.75,5.44 23.95,5.44 23.95,6.28 24.15,6.28 24.15,5.44 24.35,5.44 24.35,6.28 24.55,6.28 24.55,5.44 24.75,5.44 24.75,6.28 24.95,6.28 24.95,5.44 25.15,5.44 25.15,6.28 25.35,6.28 25.35,5.44 25.55,5.44 25.55,6.28 25.75,6.28 25.75,4.17 27.31,2.62 27.32,2.62 27.38,2.56 28.51,2.56 28.69,2.37 28.69,1.74 28.1,1.14 25.02,1.14 24.82,1.35 24.82,3.14 24.55,3.41 23.83,3.41 23.55,3.69 23.55,6.28 23.75,6.28
GND on TOP: 22.32,30.86 22.55,30.86 22.73,30.68 22.73,29.64 22.91,29.46 23.95,29.46 24.99,28.42 25.04,28.42 25.17,28.29 25.17,28.07 25.07,27.96 24.86,27.96 24.61,27.71 24.61,27.63 24.59,27.61 24.43,27.61 24.36,27.69 24.36,28.73 24.13,28.96 22.88,28.96 22.66,28.73 22.66,27.63 22.63,27.61 22.43,27.61 22.1,27.94 21.94,27.94 21.79,28.09 21.79,28.35 21.89,28.45 22.15,28.45 22.27,28.57 22.27,28.75 22.38,28.85 22.5,28.85 22.73,29.08 22.73,29.34 22.55,29.51 22.48,29.51 22.3,29.69 22.3,29.77 22.15,29.92 21.94,29.92 21.77,30.1 21.77,30.35 21.84,30.43 22.17,30.43 22.3,30.56 22.3,30.83
GND on TOP: 25.34,25.64 25.34,26.38 27.1,26.38 27.1,25.64
GND on TOP: 24.33,30.89 24.51,30.89 24.92,30.48 25.04,30.48 25.17,30.35 25.17,30.1 25.07,30 24.94,30 24.53,29.59 24.41,29.59 24.28,29.72 24.28,30.83
GND on TOP: 19.72,26.63 19.84,26.75 20.04,26.75 20.17,26.62 20.17,26.42 20.27,26.31 20.65,26.31 20.78,26.44 21.08,26.44 21.18,26.34 21.18,26.01 21.28,25.91 21.49,25.91 21.56,25.83 21.56,25.58 21.49,25.5 21.03,25.5 20.93,25.6 20.55,25.6 20.42,25.48 19.87,25.48 19.43,25.91 19.43,26.14 19.72,26.43
GND on TOP: 44.67,50.29 66.8,50.29 68.24,49.7 68.83,48.26 68.83,4.61 68.75,4.53 68.37,4.53 67.62,3.78 67.62,2.87 67.71,2.77 68.83,2.77 68.83,2.54 68.24,1.1 66.8,0.51 48.16,0.51 48.16,0.46 2.54,0.46 1.3,0.87 0.55,1.93 0.48,2.23 0.46,2.54 0.46,19 0.97,19 1.14,18.82 1.14,3.27 1.42,3 7.49,3 8.21,2.28 16,2.28 16.44,2.72 19.05,2.72 19.28,2.49 37.69,2.49 37.72,2.51 37.72,2.49 39.7,2.49 39.7,4.39 39.6,4.39 41.71,6.5 41.8,6.5 41.8,15.63 44.42,18.26 44.42,19.02 46.33,20.92 48.93,20.92 49.85,20 49.85,19.98 49.87,19.96 49.87,10.91 61.39,10.91 65,14.52 65,22.07 64.21,22.87 64.21,26.92 64.38,27.09 65.47,27.09 66.03,27.65 66.03,30.87 66.57,31.41 66.57,33.92 66.56,33.93 66.56,34.39 63.54,37.41 63.54,37.61 61.27,39.88 61.07,39.88 60.59,40.35 59.89,40.35 59.87,40.34 50.51,40.34 45.61,45.24 41.56,45.24 37.06,49.73 12.6,49.73 5.59,42.72 0.92,42.72 0.56,43.08 0.56,48.59 2.19,50.22 44.59,50.22 ; 1 cut-out
GND on BOTTOM: 20.15,30.64 20.19,30.61 20.19,30.35 20.14,30.3 20.14,30.15 19.84,29.84 19.84,29.51 19.81,29.49 19.68,29.49 19.63,29.54 19.38,29.54 19.18,29.34 19.18,29.21 19.15,29.18 18.85,29.18 18.77,29.26 18.77,29.41 18.65,29.53 18.25,29.53 18.18,29.46 16.84,29.46 16.81,29.49 16.81,29.79 17.04,30.02 17.19,30.02 17.45,30.28 17.45,32.03 17.14,32.33 17.14,33.1 17.02,33.22 16.31,33.22 16.05,32.97 16.05,32.79 15.87,32.61 15.54,32.61 15.19,32.97 15.19,34.59 15.49,34.9 16.69,34.9 17.14,35.36 17.14,35.66 17.52,36.04 22.05,36.04 22.86,35.23 22.86,34.16 22.05,33.35 20.85,33.35 20.5,32.99 20.5,32.49 20.57,32.41 20.62,32.41 20.75,32.28 20.75,32.05 20.62,31.93 19.91,31.93 19.73,31.75 19.66,31.75 19.53,31.62 19.53,31.14 19.71,30.96 19.99,30.96 20.15,30.8
GND on BOTTOM: outline of 104 points within 0.52,0.46 68.83,50.29
GND on BOTTOM: 17.52,23.72 17.52,28.42 17.63,28.52 19.56,28.52 19.58,28.55 19.58,28.88 19.61,28.9 19.94,28.9 19.96,28.88 19.96,28.57 20.17,28.37 20.17,27.48 19.99,27.3 19.63,27.3 19.51,27.18 19.52,27.16 19.4,27.05 19.4,26.64 19.78,26.26 20.6,26.26 20.78,26.44 21.16,26.44 21.28,26.57 21.28,26.67 21.33,26.72 21.59,26.72 21.64,26.67 21.64,26.39 21.28,26.03 21.28,25.53 21.57,25.25 21.57,22.99 21.16,22.58 18.66,22.58
GND on BOTTOM: 9.24,21.28 12.16,21.28 12.93,20.52 12.93,18.64 12.95,18.62 12.95,17.12 14.01,16.06 17.61,16.06 18.74,14.93 18.74,13.77 18.49,13.51 18.08,13.51 18.06,13.54 15.11,13.54 14.81,13.23 14.81,11.05 15.47,10.39 15.47,10.31 15.49,10.34 18.24,10.34 18.67,9.91 18.67,7.77 18.08,7.19 16.03,7.19 15.97,7.24 11.81,7.24 11.56,7.49 8.2,7.49 8.13,7.57 7.11,7.57 6.76,7.92 6.76,13.41 6.99,13.64 11.25,13.64 11.43,13.46 11.43,13.13 11.58,12.98 12.74,12.98 12.85,13.09 12.85,14.81 11.86,15.8 9.98,15.8 9.37,16.41 9.37,17.17 8.48,18.06 8.48,20.52 ; 9 cut-outs
GND on BOTTOM: 6.04,5.43 9.22,5.43 9.35,5.3 9.35,4.34 9.41,4.28 9.51,4.28 9.81,3.97 9.81,3.25 9.74,3.18 9.02,3.18 8.89,3.05 6.09,3.05 5.66,3.48 5.66,5.05 ; 2 cut-outs
GND on L3_IN1: 47.81,50.29 66.8,50.29 68.24,49.7 68.83,48.26 68.83,2.54 68.24,1.1 66.8,0.51 47.37,0.51 47.37,0.51 29.36,0.51 29.36,0.46 2.54,0.46 1.07,1.07 0.46,2.54 0.46,19.02 0.86,19.02 0.99,18.9 0.99,3.83 3.83,0.99 27.1,0.99 28.52,2.41 29.01,2.41 29.11,2.51 38.72,2.51 40.86,4.65 40.86,9 47.69,15.84 49.63,15.84 49.94,15.53 49.94,11.22 57.17,18.44 67.34,18.44 67.34,21.84 66.91,22.26 64.47,22.26 64.2,22.53 64.2,24.97 63.56,25.61 52.98,25.61 50.6,27.99 48.82,27.99 47.92,28.89 47.92,41.72 40.08,49.56 12.96,49.56 11.1,47.7 11.1,42.06 10.39,41.35 0.92,41.35 0.53,41.73 0.53,48.31 2.49,50.27 47.81,50.27
GND on L4_PWR_1: 66.8,50.29 68.24,49.7 68.83,48.26 68.83,2.54 68.24,1.1 66.8,0.51 46.3,0.51 46.3,0.51 2.54,0.51 1.1,1.1 0.51,2.54 0.51,48.26 1.1,49.7 2.54,50.29 47.65,50.29 ; 1 cut-out
GND on L5_PWR_2: 0.46,48.26 1.07,49.73 2.54,50.34 48.26,50.34 48.49,50.33 48.72,50.29 66.8,50.29 68.24,49.7 68.83,48.26 68.83,2.54 68.24,1.1 66.8,0.51 48.73,0.51 48.73,0.51 48.5,0.47 48.26,0.46 39.73,0.46 39.73,1.65 43.26,5.18 43.26,10.42 43.64,10.8 43.64,14.15 43.28,14.51 43.28,14.54 40.42,17.41 40.42,24.2 46.61,30.39 46.61,37.53 46.13,38.01 41.85,38.01 39.06,40.81 39.06,43.45 38.46,44.05 21.95,44.05 21.18,43.28 21.18,36.55 20.88,36.25 20.88,32.67 21.74,31.8 25.35,31.8 26.34,30.81 29.31,30.81 30.2,29.92 30.2,27.87 29.39,27.05 29.39,24.06 27.33,22 27.33,17.98 23.27,13.92 15.83,13.92 13.46,16.28 7.24,16.28 6.14,15.19 5.48,15.19 4.9,14.6 4.9,12.29 5.13,12.06 6.96,12.06 7.87,12.98 13.26,12.98 13.49,12.75 13.49,9.04 12.06,7.62 5.92,7.62 5.07,8.47 4.15,8.47 3.35,7.67 3.35,1.73 3.86,1.22 3.86,0.63 3.73,0.51 3,0.51 3,0.46 2.54,0.46 1.07,1.07 0.46,2.54 ; 3 cut-outs
VDD_ARM_0V9 on TOP: 12.93,19.91 15.9,19.91 16.38,19.43 16.38,16.76 16.33,16.71 14.91,16.71 14.17,15.98 13.03,15.98 12.85,16.15 12.85,19.84
VDD_ARM_0V9 on TOP: 22.9,28.85 24.06,28.85 24.25,28.66 24.25,27.58 24.39,27.43 25.09,27.43 25.19,27.33 25.19,26.98 25.13,26.93 24.75,26.93 24.68,26.85 24.68,26.47 24.68,26.46 24.68,26.15 24.55,26.02 24.34,26.02 24.21,26.15 24.21,26.38 24.01,26.58 22.92,26.58 22.75,26.75 22.75,28.7
VDD_ARM_0V9 on BOTTOM: 13.49,17.2 13.49,19.05 13.69,19.25 17.17,19.25 17.35,19.07 17.35,16.76 17.07,16.48 14.2,16.48 ; 2 cut-outs
VDD_ARM_0V9 on L4_PWR_1: 17.5,18.97 22.14,23.65 22.14,25.83 22.68,26.38 22.68,28.8 22.89,29 24.17,29 24.4,28.77 24.4,28.51 25.17,27.74 28.4,27.74 28.4,22.99 20.32,14.91 13.09,14.91 12.56,15.44 12.56,17.51 14.02,18.97
VDD_SOC&DRAM&PU_0V9 on TOP: 19.47,13.47 19.81,13.13 19.81,11.18 19.58,10.95 15.92,10.95 15.77,11.1 15.77,12.29 15.87,12.39 17.47,12.39 17.86,12.78 17.86,13.41 17.93,13.47
VDD_SOC&DRAM&PU_0V9 on TOP: outline of 82 points within 20.88,26.57 25.75,31.88 ; 1 cut-out
VDD_SOC&DRAM&PU_0V9 on BOTTOM: 15.42,13.33 18.51,13.33 19.2,12.65 19.2,11.02 19,10.82 15.52,10.82 15.34,11 15.34,13.26 ; 2 cut-outs
VDD_SOC&DRAM&PU_0V9 on L4_PWR_1: 28.58,27.99 25.27,27.99 24.65,28.61 24.65,28.88 24.27,29.25 22.94,29.25 22.56,28.88 22.56,27.08 22.43,26.95 21.92,26.95 21.26,27.61 21.26,31.04 21.95,31.73 22.04,31.73 22.15,31.61 23.04,31.61 23.25,31.82 23.25,32.41 23.66,32.82 23.66,35.07 24.51,35.92 24.51,37.16 25.99,38.64 30.23,38.64 31.04,39.45 36.02,39.45 38.18,37.29 38.18,31.37 39.17,30.38 39.17,27.08 41.33,24.92 41.33,19.15 39.93,17.76 39.93,13.21 38.86,12.14 38.86,8.61 36.25,6 15.59,6 14.98,6.6 14.98,14.51 15.06,14.58 20.41,14.58 28.77,22.94 28.77,27.8
VDDA_1V8 on BOTTOM: 23.85,20.73 23.85,23.21 23.94,23.3 24.62,23.3 24.62,21.92 25.2,21.33 25.2,19.66 21.33,15.8 21.33,14.22 20.6,13.49 20.16,13.49 20.06,13.59 20.06,16.94
VDDA_1V8 on L3_IN1: 26.74,29.67 26.74,29.06 26.1,28.41 26.1,27.85 25.61,27.37 25.06,27.37 24.76,27.08 24.38,27.08 23.72,26.42 23.72,26.14 23.57,25.98 23.11,25.98 22.43,26.67 22.43,31.72 22.77,32.07 22.77,32.9 23.24,33.37 23.82,33.37 24.41,32.79 24.41,32.26 25.2,31.47 25.96,31.47 26.11,31.32 26.11,30.3
VIN_LDO_CAP on TOP: 52.92,37.72 54.1,37.72 54.2,37.62 54.2,33.68 54.18,33.67 52.71,33.67 52.56,33.82 52.56,37.36
LX1 on TOP: 13.03,11.45 15.09,11.45 16.13,10.41 17.75,10.41 17.88,10.29 17.88,9.12 17.83,9.07 15.7,9.07 15.02,9.74 15.02,10.1 14.3,10.82 13.05,10.82 12.98,10.9 12.98,11.4
LX2 on TOP: 10.95,18.08 12.14,18.08 12.19,18.03 12.19,15.39 11.91,15.11 11.91,13.74 11.86,13.69 11.33,13.69 11.28,13.74 11.28,15.44 10.92,15.8 10.92,18.06
LX4 on TOP: 8.94,7.77 9.47,7.77 9.55,7.7 9.55,5.77 8.99,5.21 8.99,3.25 8.86,3.12 7.82,3.12 7.67,3.28 7.67,5.28 8.27,5.88 8.44,5.88 8.91,6.35 8.91,7.75
LX5 on TOP: 6.88,7.75 7.49,7.75 7.52,7.72 7.52,6.02 7.21,5.71 7.21,5.51 6.86,5.16 6.86,3.43 6.04,3.43 5.99,3.48 5.99,5.77 6.78,6.55 6.78,7.64
LX6 on TOP: 7.87,18.01 9.14,18.01 9.14,16.46 9.9,15.7 9.9,13.72 9.88,13.69 9.37,13.69 9.29,13.77 9.29,14.76 8.48,15.57 8.13,15.57 7.8,15.9 7.8,17.93
NVCC_1V8 on BOTTOM (solid shape): 26.15,5.44 26.35,5.44 26.35,6.28 26.55,6.28 26.55,5.44 26.75,5.44 26.75,6.28 26.95,6.28 26.95,5.44 27.15,5.44 27.15,6.28 27.35,6.28 27.35,5.44 27.55,5.44 27.55,6.28 27.75,6.28 27.75,5.44 27.95,5.44 27.95,6.28 28.15,6.28 28.15,5.44 28.35,5.44 28.35,6.28 28.55,6.28 28.55,5.44 28.75,5.44 28.75,6.28 28.95,6.28 28.95,3.28 28.68,3.01 27.7,3.01 26.53,4.17 25.95,4.17 25.95,6.28 26.15,6.28
NVCC_1V8 on TOP: 4.14,7.49 5.28,7.49 5.61,7.16 5.61,5.61 5.28,5.28 5.28,3.35 5.21,3.28 4.27,3.28 3.91,3.63 3.91,7.26
NVCC_1V8 on BOTTOM: 3.4,6.91 5.21,6.91 5.41,6.7 5.41,5.36 5.13,5.08 5.13,3.89 4.95,3.71 3.94,3.71 3.3,4.34 3.3,6.81 ; 1 cut-out
NVCC_1V8 on L3_IN1: 1.88,32.84 3.76,32.84 4.04,32.56 4.04,32.28 3.81,32.05 3.38,32.05 2.79,31.47 2.79,29.21 3,29.01 3,27.74 3.34,27.39 9.66,27.39 10.08,26.97 10.72,26.97 11.83,25.86 11.83,23.72 9.5,21.39 5.79,21.39 4.34,19.94 4.34,10.08 6.5,7.92 6.5,5.26 5.71,4.47 4.01,4.47 2.59,5.89 2.59,20.83 1.5,21.92 1.5,32.46
NVCC_1V8 on L4_PWR_1: 2.54,1.27 2.54,7.8 2.84,8.1 6.09,8.1 6.32,7.87 6.32,7.11 7.79,5.64 9.47,5.64 10.32,6.5 14.64,6.5 15.5,5.64 20.42,5.64 20.55,5.77 36.4,5.77 39.12,8.49 39.12,11.99 40.18,13.06 40.18,17.63 41.61,19.05 41.61,25.12 39.4,27.33 39.4,30.61 38.48,31.52 38.48,37.26 36.07,39.68 30.99,39.68 30.13,38.81 25.88,38.81 24.32,37.25 24.32,36.08 23.41,35.17 23.41,32.95 23.05,32.58 23.05,31.97 22.94,31.87 22.14,31.87 22.14,37.77 22.71,37.77 28.71,43.77 28.71,45.2 29.02,45.51 41.12,45.51 46.13,40.5 46.13,22.35 46.2,22.29 46.2,17.75 46.19,17.73 46.19,6.79 40.67,1.27
NVCC_3V3 on BOTTOM (solid shape): 26.12,24.05 26.12,23.44 28.26,21.31 28.26,20.47 28.95,19.78 28.95,8.65 28.75,8.65 28.75,9.49 28.55,9.49 28.55,8.65 28.35,8.65 28.35,9.49 28.15,9.49 28.15,8.65 27.95,8.65 27.95,9.49 27.75,9.49 27.75,8.65 27.55,8.65 27.55,9.49 27.35,9.49 27.35,8.65 27.15,8.65 27.15,9.49 26.95,9.49 26.95,8.65 26.75,8.65 26.75,9.49 26.55,9.49 26.55,8.65 26.35,8.65 26.35,9.49 26.15,9.49 26.15,8.65 25.95,8.65 25.95,10.35 26.2,10.61 26.2,11.92 26.16,11.96 26.16,22.18 25.35,22.99 25.35,23.96 25.56,24.18 25.99,24.18
NVCC_3V3 on TOP: 9.7,7.75 10.29,7.75 10.34,7.7 10.34,6.27 10.95,5.66 11.4,5.66 11.71,5.36 12.09,5.36 12.27,5.18 12.27,3.33 12.01,3.07 9.88,3.07 9.7,3.25
NVCC_3V3 on BOTTOM: 54.61,41.97 61.06,41.97 67.13,35.9 67.13,31.99 66.06,30.92 65.34,30.92 65.07,31.19 65.07,34.96 59.55,40.48 59.55,40.66 59.33,40.88 55.98,40.88 49.04,33.94 45.55,33.94 45.23,34.27 45.23,34.91 45.45,35.13 47.78,35.13
NVCC_3V3 on BOTTOM: 10.29,5.36 12.27,5.36 12.55,5.08 12.55,3.48 12.32,3.25 10.09,3.25 10.07,3.27 10.07,5.15 ; 1 cut-out
NVCC_3V3 on L5_PWR_2: 21.87,32 22.73,32 23.04,32.31 24.97,32.31 25.75,31.52 26.97,31.52 26.97,32.18 27.61,32.82 27.61,36.5 26.31,37.79 26.31,40.36 27.43,41.48 34.49,41.48 35.45,40.51 35.45,36.51 33.68,34.73 33.68,19.6 27.32,13.25 24.98,13.25 24.98,4.7 23.94,3.66 21.24,3.66 20.14,4.75 8.4,4.75 5.28,7.88 5.11,7.88 4.95,8.03 4.95,8.05 4.8,8.2 4.24,8.2 3.61,7.57 3.61,1.73 4.32,1.02 38.69,1.02 42.9,5.23 42.9,10.52 43.33,10.95 43.33,14.07 43.07,14.34 43.07,14.35 40.33,17.09 40.33,24.57 46.4,30.64 46.4,37.34 45.97,37.78 41.76,37.78 38.87,40.66 38.87,43.23 38.34,43.77 22.02,43.77 21.39,43.13 21.39,36.3 21.23,36.14 21.23,33.73 21.18,33.68 21.18,32.64 21.31,32.51 21.36,32.51
NVCC_DRAM_1V1 on TOP: 3.83,19.99 6.93,19.99 7.26,19.66 7.26,16.08 7.08,15.9 5.79,15.9 5.61,16.08 5.61,17.86 5.21,18.26 4.01,18.26 3.66,18.62 3.66,19.81
NVCC_DRAM_1V1 on TOP: 20.35,31.88 20.7,31.88 20.85,32.03 21.21,32.03 21.24,32.01 21.24,31.47 21.11,31.35 21.11,29.64 20.7,29.24 20.7,28.98 20.85,28.83 21.01,28.83 21.08,28.75 21.08,26.85 20.75,26.52 20.35,26.52 20.24,26.62 20.24,28.12 20.27,28.14 20.27,28.73 20.04,28.96 19.38,28.96 19.28,29.06 19.28,29.31 19.41,29.44 20.07,29.44 20.27,29.64 20.27,31.8
NVCC_DRAM_1V1 on BOTTOM: 19.97,31.83 20.4,31.83 20.45,31.88 20.73,31.88 20.83,31.98 21.21,31.98 21.29,31.9 21.29,31.6 21.16,31.47 21.16,30.99 20.83,30.66 20.83,29.69 21.21,29.31 21.21,28.93 21.08,28.81 20.93,28.81 20.73,28.6 20.73,26.72 20.52,26.52 19.84,26.52 19.66,26.7 19.66,27.05 19.79,27.18 20.07,27.18 20.35,27.46 20.35,28.45 20.04,28.75 20.04,28.98 19.97,29.06 19.64,29.06 19.31,28.73 19.31,28.65 19.05,28.65 18.92,28.78 18.92,28.88 19.08,29.03 19.23,29.03 19.33,29.14 19.33,29.29 19.48,29.44 19.91,29.44 20.14,29.67 20.14,30 20.27,30.13 20.27,30.84 20.02,31.09 19.81,31.09 19.66,31.24 19.66,31.57 19.81,31.73 19.86,31.73
NVCC_DRAM_1V1 on BOTTOM: 5.1,20.27 7.57,20.27 8.05,19.79 8.05,18.36 7.8,18.11 5.38,18.11 4.95,18.54 4.95,20.12 ; 1 cut-out
NVCC_DRAM_1V1 on L3_IN1: 22.02,27.84 22.02,26.75 21.41,26.14 20.34,26.14 19.48,27 19.48,27.79 19.25,28.02 19.25,28.37 19.26,28.37 19.26,28.47 19.35,28.56 19.58,28.56 19.65,28.63 21.23,28.63
NVCC_DRAM_1V1 on L3_IN1: 19.95,32.27 21.35,32.27 22.19,31.43 22.19,29.18 22.06,29.05 19.31,29.05 19.25,29.11 19.25,30.37 19.71,30.83 19.71,32.03
NVCC_DRAM_1V1 on L4_PWR_1: 1.02,19.89 1.02,38.81 1.7,39.5 20.27,39.5 21.88,37.84 21.88,31.9 21.01,31.03 21.01,27.68 21.88,26.8 21.88,23.76 17.45,19.28 14.02,19.28 12.34,17.6 12.34,15.93 3.27,15.93 1.17,18.03 1.17,19.74
NVCC_ENET on BOTTOM: 27.33,26.97 28.19,26.97 28.27,26.9 28.27,24.87 28.01,24.61 27,24.61 26.67,24.94 26.67,25.81 26.95,26.09 26.95,26.31 27.28,26.64 27.28,26.92
